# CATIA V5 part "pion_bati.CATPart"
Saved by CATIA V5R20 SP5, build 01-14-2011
Part number: pion_bati
Bounding box of the stored display mesh (mm): x -171.37 to -161.37, y -44.22 to -27.61, z 127.087 to 137.087
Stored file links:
  F:\iao\catia\projet iao\pion_bati.CATPart
  F:\iao\catia\projet iao\fhartmann.CATProduct
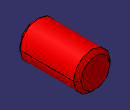
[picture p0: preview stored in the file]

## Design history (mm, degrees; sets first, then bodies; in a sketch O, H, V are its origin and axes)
External parameters (linked from other documents)
  External.bati_epaisseur_languette = 10 mm
  External.bielle1_epaisseur = 6.61 mm
  External.bielle_diametre_int = 10 mm
Set1
  Plane1: linked copy from another document
  Point1: linked copy from another document
Body1 (main body)
  Sketch1 on Plane1, origin (0, -44.22, 0), H (-1, 0, 0), V (0, 0, 1)
    circle A1 centre (166.3695, 132.087) radius 5
    point P1 (166.3695, 132.087)
    reference projected point E1 (166.3695, 132.087) from Point1
    radius A1 = 5 {= External.bielle_diametre_int /2}
    coincidence: P1 E1
  Pad1: profile Sketch1, direction (0, 1, 0), length 16.61 {= External.bati_epaisseur_languette +External.bielle1_epaisseur}
  Chamfer1: length 1, angle 45, on edge [start face of Pad1 | face of Pad1 from Sketch1.A1]; edge [face of Pad1 from Sketch1.A1 | end face of Pad1]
